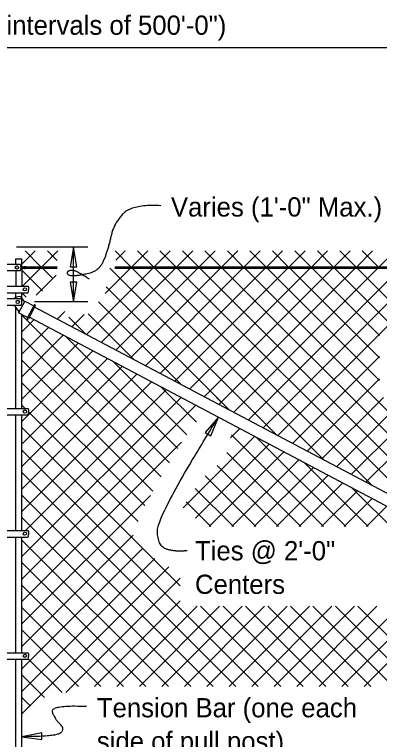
# Model space of a CAD drawing. Extents: x 110698 to 110915, y 110390 to 110472.
# Drawn here: x 110885.02 to 110888.85, y 110461.82 to 110469.42 of the extents above; entities that cross this region are included whole.
import ezdxf

# ---------------------------------------------------------------- set-up
doc = ezdxf.new("R2010")
doc.units = 0
for name, color, linetype in [('Border', 7, 'Continuous'), ('PlotBorder_dp', 7, 'Continuous'), ('SheetBorder_dp', 7, 'Continuous'), ('TextMisc', 7, 'Continuous')]:
    doc.layers.add(name, color=color, linetype=linetype)

msp = doc.modelspace()

# ---------------------------------------------------------------- linework, layer by layer
at = {"layer": 'PlotBorder_dp'}
for p, q in [((110874.8293, 110469.0764), (110894.8293, 110469.0764)), ((110885.7916, 110466.9853), (110885.0426, 110466.9853)), ((110885.6416, 110466.4105), (110885.6416, 110466.9853)), ((110885.7916, 110466.4105), (110885.2325, 110466.4105))]:
    msp.add_line(p, q, dxfattribs=at)
for points in [[(110885.6416, 110466.9853), (110885.6063, 110466.7771), (110885.6769, 110466.7771)], [(110885.6416, 110466.4105), (110885.6769, 110466.6187), (110885.6063, 110466.6187)], [(110887.1593, 110465.2015), (110887.0203, 110465.0425), (110887.0804, 110465.0055)], [(110885.1003, 110461.8521), (110885.3095, 110461.8231), (110885.3074, 110461.8936)]]:
    msp.add_lwpolyline(points, close=True, dxfattribs=at)
for points in [[(110886.5552, 110467.4191), (110886.2572, 110467.4351), (110886.0625, 110467.2327), (110886.0028, 110466.9563), (110885.9105, 110466.7344), (110885.689, 110466.6836), (110885.5782, 110466.6836), (110885.5782, 110466.7437), (110885.6705, 110466.7437), (110885.8043, 110466.6513)], [(110886.8318, 110463.8019), (110886.7009, 110463.7877), (110886.5179, 110463.855), (110886.5264, 110464.1816), (110887.1593, 110465.2015)], [(110885.7777, 110462.1679), (110885.3789, 110462.1857), (110885.4592, 110462.0189), (110885.5455, 110461.9415), (110885.4771, 110461.8521), (110885.1002, 110461.8521)]]:
    msp.add_open_spline(points, degree=2, dxfattribs=at)
at = {"layer": 'SheetBorder_dp'}
for p, q in [((110885.1002, 110466.8053), (110885.2403, 110466.9454)), ((110885.1329, 110466.9454), (110885.2996, 110466.7787)), ((110885.3094, 110466.7787), (110885.476, 110466.9454)), ((110885.3686, 110466.9454), (110885.4708, 110466.8432)), ((110886.0757, 110466.9454), (110886.2424, 110466.7787)), ((110886.0861, 110466.8483), (110886.1831, 110466.9454)), ((110886.2522, 110466.7787), (110886.4188, 110466.9454)), ((110886.3114, 110466.9454), (110886.4781, 110466.7787)), ((110886.4879, 110466.7787), (110886.6546, 110466.9454)), ((110886.5471, 110466.9454), (110886.7138, 110466.7787)), ((110886.7236, 110466.7787), (110886.8903, 110466.9454)), ((110886.7828, 110466.9454), (110886.9495, 110466.7787)), ((110886.9593, 110466.7787), (110887.126, 110466.9454)), ((110887.0185, 110466.9454), (110887.1852, 110466.7787)), ((110887.195, 110466.7787), (110887.3617, 110466.9454)), ((110887.2542, 110466.9454), (110887.4209, 110466.7787)), ((110887.4307, 110466.7787), (110887.5974, 110466.9454)), ((110887.4899, 110466.9454), (110887.6566, 110466.7787)), ((110887.6664, 110466.7787), (110887.8331, 110466.9454)), ((110887.7256, 110466.9454), (110887.8923, 110466.7787)), ((110887.9021, 110466.7787), (110888.0688, 110466.9454)), ((110887.9613, 110466.9454), (110888.128, 110466.7787)), ((110888.1378, 110466.7787), (110888.3045, 110466.9454)), ((110888.197, 110466.9454), (110888.3637, 110466.7787)), ((110888.3735, 110466.7787), (110888.5402, 110466.9454)), ((110888.4327, 110466.9454), (110888.5994, 110466.7787)), ((110888.6092, 110466.7787), (110888.7759, 110466.9454)), ((110888.6684, 110466.9454), (110888.8351, 110466.7787)), ((110888.8449, 110466.7787), (110889.0116, 110466.9454)), ((110885.1002, 110466.7423), (110885.3169, 110466.5257)), ((110885.1053, 110466.5746), (110885.2946, 110466.764)), ((110885.3143, 110466.764), (110885.4229, 110466.6553)), ((110885.7769, 110466.0677), (110886.4731, 110466.764)), ((110885.9311, 110465.9862), (110886.7088, 110466.764)), ((110885.9719, 110466.4984), (110886.2374, 110466.764)), ((110886.0214, 110466.764), (110887.772, 110465.0134)), ((110886.0853, 110465.9047), (110886.9445, 110466.764)), ((110886.2395, 110465.8232), (110887.1802, 110466.764)), ((110886.2571, 110466.764), (110888.2719, 110464.7492)), ((110886.3937, 110465.7417), (110887.4159, 110466.764)), ((110886.4928, 110466.764), (110888.7717, 110464.4851)), ((110886.5479, 110465.6602), (110887.6516, 110466.764)), ((110886.7021, 110465.5787), (110887.8873, 110466.764)), ((110886.7285, 110466.764), (110889.2716, 110464.2209)), ((110886.8563, 110465.4972), (110888.1231, 110466.764)), ((110886.9642, 110466.764), (110889.7714, 110463.9568)), ((110887.0106, 110465.4158), (110888.3588, 110466.764)), ((110887.1648, 110465.3343), (110888.5945, 110466.764)), ((110887.1999, 110466.764), (110890.0805, 110463.8834)), ((110887.319, 110465.2528), (110888.8302, 110466.764)), ((110887.4356, 110466.764), (110890.0805, 110464.1191)), ((110887.4732, 110465.1713), (110889.0659, 110466.764)), ((110887.6274, 110465.0898), (110889.3016, 110466.764)), ((110887.6713, 110466.764), (110888.8471, 110465.5882)), ((110887.7816, 110465.0083), (110889.5373, 110466.764)), ((110887.907, 110466.764), (110888.8471, 110465.8239)), ((110888.1427, 110466.764), (110888.8471, 110466.0596)), ((110888.3784, 110466.764), (110889.0161, 110466.1263)), ((110888.6141, 110466.764), (110889.2518, 110466.1263)), ((110885.2482, 110466.4818), (110885.4579, 110466.6915)), ((110885.1002, 110466.5066), (110885.1457, 110466.4612)), ((110885.9827, 110466.5669), (110887.2722, 110465.2775)), ((110885.902, 110466.412), (110886.7723, 110465.5417)), ((110885.4685, 110466.2307), (110885.5489, 110466.3111)), ((110885.6227, 110466.1492), (110885.7533, 110466.2798)), ((110885.793, 110466.2852), (110886.2725, 110465.8058)), ((110885.1002, 110466.2709), (110886.6464, 110464.7247)), ((110885.1002, 110466.0981), (110885.2255, 110466.2234)), ((110885.592, 110466.2506), (110885.7726, 110466.07)), ((110885.1002, 110465.8624), (110885.3797, 110466.1419)), ((110885.1002, 110465.6267), (110885.5339, 110466.0604)), ((110885.1002, 110466.0352), (110886.5601, 110464.5754)), ((110885.1002, 110465.391), (110885.6881, 110465.9789)), ((110885.5604, 110466.0464), (110886.7328, 110464.8741)), ((110885.1002, 110465.1553), (110885.8423, 110465.8975)), ((110887.9358, 110464.9268), (110888.8471, 110465.8381)), ((110885.1002, 110465.7995), (110886.4737, 110464.426)), ((110885.1067, 110464.9261), (110885.9965, 110465.816)), ((110886.0603, 110465.7823), (110886.8273, 110465.0153)), ((110885.1002, 110464.6839), (110886.1508, 110465.7345)), ((110885.1002, 110464.4482), (110886.305, 110465.653)), ((110888.09, 110464.8453), (110888.8471, 110465.6024)), ((110885.1002, 110464.2125), (110886.4592, 110465.5715)), ((110885.1002, 110465.5638), (110886.3874, 110464.2767)), ((110886.5601, 110465.5181), (110886.9298, 110465.1484)), ((110885.137, 110464.0136), (110886.6134, 110465.49)), ((110885.1002, 110463.7411), (110886.7676, 110465.4085)), ((110887.1404, 110465.4092), (110887.2722, 110465.2775)), ((110888.2442, 110464.7638), (110888.8896, 110465.4092)), ((110888.3984, 110464.6823), (110889.1253, 110465.4092)), ((110888.3984, 110464.6823), (110889.1253, 110465.4092)), ((110888.5526, 110464.6008), (110889.361, 110465.4092)), ((110888.5526, 110464.6008), (110889.361, 110465.4092)), ((110888.7069, 110464.5193), (110889.5967, 110465.4092)), ((110888.7069, 110464.5193), (110889.5967, 110465.4092)), ((110885.1002, 110465.3281), (110885.1343, 110465.2941)), ((110885.1002, 110463.5054), (110886.9218, 110465.327)), ((110885.1726, 110465.2558), (110886.32, 110464.1083)), ((110885.1002, 110465.0924), (110886.7577, 110463.435)), ((110887.2874, 110464.9855), (110887.3844, 110465.0825)), ((110886.7889, 110464.2513), (110887.5387, 110465.001)), ((110887.2958, 110465.0182), (110888.2597, 110464.0543)), ((110887.5598, 110464.9899), (110888.4954, 110464.0543)), ((110885.1002, 110463.2697), (110886.7715, 110464.941)), ((110886.9184, 110464.1451), (110887.6929, 110464.9196)), ((110885.1002, 110464.8567), (110887.5776, 110462.3794)), ((110887.0633, 110464.0543), (110887.8471, 110464.8381)), ((110887.2479, 110464.8304), (110888.024, 110464.0543)), ((110887.1456, 110464.6969), (110887.7883, 110464.0543)), ((110887.299, 110464.0543), (110888.0013, 110464.7566)), ((110888.0596, 110464.7257), (110888.7311, 110464.0543)), ((110885.1002, 110464.621), (110887.3419, 110462.3794)), ((110887.5347, 110464.0543), (110888.1555, 110464.6751)), ((110887.0207, 110464.5861), (110887.5526, 110464.0543)), ((110887.7704, 110464.0543), (110888.3097, 110464.5936)), ((110886.9162, 110464.4549), (110887.3168, 110464.0543)), ((110888.0061, 110464.0543), (110888.4639, 110464.5121)), ((110888.5595, 110464.4616), (110891.8943, 110461.1268)), ((110885.1002, 110464.3853), (110887.1062, 110462.3794)), ((110885.1002, 110463.034), (110886.4484, 110464.3822)), ((110888.2418, 110464.0543), (110888.6181, 110464.4306)), ((110886.8224, 110464.313), (110887.0811, 110464.0543)), ((110888.4775, 110464.0543), (110888.7723, 110464.3491)), ((110888.7132, 110464.0543), (110888.9266, 110464.2676)), ((110885.1002, 110464.1496), (110886.8705, 110462.3794)), ((110885.1002, 110462.7983), (110886.2655, 110463.9636)), ((110885.1002, 110463.9139), (110886.6348, 110462.3794)), ((110888.2168, 110462.3794), (110889.6976, 110463.8602)), ((110885.1002, 110462.5626), (110886.3602, 110463.8226)), ((110888.4525, 110462.3794), (110889.8518, 110463.7787)), ((110885.1002, 110462.3269), (110886.4929, 110463.7196)), ((110888.6882, 110462.3794), (110890.006, 110463.6972)), ((110885.1002, 110463.6782), (110886.3991, 110462.3794)), ((110885.1002, 110462.0912), (110886.6417, 110463.6327)), ((110885.5593, 110462.3145), (110886.7577, 110463.513)), ((110885.1002, 110463.4425), (110886.1634, 110462.3794)), ((110885.8598, 110462.3794), (110886.7577, 110463.2773)), ((110885.1002, 110463.2068), (110885.9277, 110462.3794)), ((110886.0955, 110462.3794), (110886.9363, 110463.2202)), ((110886.3312, 110462.3794), (110887.172, 110463.2202)), ((110886.5669, 110462.3794), (110887.4077, 110463.2202)), ((110886.8026, 110462.3794), (110887.6434, 110463.2202)), ((110886.9725, 110463.2202), (110887.8133, 110462.3794)), ((110887.0383, 110462.3794), (110887.8791, 110463.2202)), ((110887.2082, 110463.2202), (110888.049, 110462.3794)), ((110887.274, 110462.3794), (110888.1148, 110463.2202)), ((110887.4439, 110463.2202), (110888.2847, 110462.3794)), ((110887.5097, 110462.3794), (110888.3505, 110463.2202)), ((110887.6796, 110463.2202), (110888.5204, 110462.3794)), ((110887.7454, 110462.3794), (110888.5862, 110463.2202)), ((110887.9153, 110463.2202), (110888.7561, 110462.3794)), ((110887.9811, 110462.3794), (110888.8219, 110463.2202)), ((110888.151, 110463.2202), (110888.9918, 110462.3794)), ((110888.3867, 110463.2202), (110890.4801, 110461.1268)), ((110888.6224, 110463.2202), (110890.7158, 110461.1268)), ((110885.1002, 110462.9711), (110885.692, 110462.3794)), ((110885.166, 110462.6696), (110885.5202, 110462.3155)), ((110885.1002, 110462.4997), (110885.3381, 110462.2618)), ((110885.1002, 110462.264), (110885.1905, 110462.1737))]:
    msp.add_line(p, q, dxfattribs=at)
at = {"layer": 'TextMisc'}
for p, q in [((110885.0377, 110466.8058), (110885.0377, 110466.862)), ((110885.0377, 110466.862), (110885.1002, 110466.862)), ((110885.0377, 110466.8058), (110885.0377, 110466.862)), ((110885.0377, 110466.862), (110885.1002, 110466.862)), ((110885.1002, 110466.7818), (110885.1002, 110466.862)), ((110885.1002, 110466.7818), (110885.1002, 110466.862)), ((110884.6737, 110466.8058), (110885.0834, 110466.8058)), ((110884.6737, 110466.7381), (110885.0831, 110466.7381)), ((110885.0377, 110466.7381), (110885.0377, 110466.5746)), ((110885.0377, 110466.7381), (110885.0377, 110466.5746)), ((110885.0907, 110466.7833), (110885.1199, 110466.7787)), ((110885.0908, 110466.7833), (110885.1201, 110466.7787)), ((110885.0912, 110466.7629), (110885.1248, 110466.7685)), ((110885.0913, 110466.7783), (110885.1173, 110466.7743)), ((110885.0913, 110466.7629), (110885.1249, 110466.7685)), ((110885.0914, 110466.7783), (110885.1174, 110466.7743)), ((110885.0916, 110466.7677), (110885.1215, 110466.7726)), ((110885.0917, 110466.7677), (110885.1216, 110466.7726)), ((110885.1002, 110466.7769), (110885.1002, 110466.7691)), ((110885.1002, 110466.7769), (110885.1002, 110466.7691)), ((110885.1002, 110466.7644), (110885.1002, 110466.5746)), ((110885.1002, 110466.7644), (110885.1002, 110466.5746)), ((110885.1112, 110466.764), (110885.4704, 110466.764)), ((110885.1126, 110466.7787), (110885.4704, 110466.7787)), ((110886.0734, 110466.7787), (110894.5084, 110466.7787)), ((110886.0734, 110466.764), (110894.535, 110466.764)), ((110884.6737, 110466.5746), (110885.1647, 110466.5746)), ((110884.6737, 110466.507), (110885.164, 110466.507)), ((110885.0377, 110466.458), (110885.0377, 110466.5069)), ((110885.1002, 110466.4503), (110885.1002, 110466.5069)), ((110884.567, 110466.445), (110885.0918, 110466.445)), ((110885.1259, 110466.411), (110885.0912, 110466.4641)), ((110884.567, 110466.3772), (110885.0918, 110466.3772)), ((110885.0699, 110466.305), (110885.023, 110466.3767)), ((110885.0377, 110465.2941), (110885.0377, 110466.3542)), ((110885.1294, 110466.4176), (110885.0657, 110466.297)), ((110885.1294, 110466.4176), (110885.2237, 110466.3677)), ((110885.2283, 110466.3764), (110885.1558, 110466.2392)), ((110885.2402, 110466.3701), (110885.1677, 110466.233)), ((110894.482, 110461.4674), (110885.2324, 110466.3554)), ((110885.16, 110466.2471), (110885.0657, 110466.297)), ((110885.1002, 110465.2941), (110885.1002, 110466.2787)), ((110894.426, 110461.3615), (110885.1764, 110466.2494)), ((110885.0377, 110465.2941), (110885.0377, 110465.8594)), ((110885.1002, 110465.2941), (110885.1002, 110465.8247)), ((110884.6737, 110465.2941), (110885.1647, 110465.2941)), ((110884.6737, 110465.2265), (110885.164, 110465.2265)), ((110885.0377, 110464.0135), (110885.0377, 110465.2265)), ((110885.1002, 110464.0135), (110885.1002, 110465.2265)), ((110884.6737, 110464.0135), (110885.1647, 110464.0135)), ((110884.6737, 110463.9459), (110885.164, 110463.9459)), ((110885.0377, 110462.733), (110885.0377, 110463.9459)), ((110885.1002, 110462.733), (110885.1002, 110463.9459)), ((110884.6737, 110462.733), (110885.1647, 110462.733)), ((110884.6737, 110462.6654), (110885.164, 110462.6654)), ((110885.0377, 110461.4526), (110885.0377, 110462.6654)), ((110885.1002, 110461.4526), (110885.1002, 110462.6654))]:
    msp.add_line(p, q, dxfattribs=at)
for centre, start, end in [((110885.2341, 110466.3732), 332.14902, 152.14902), ((110885.1616, 110466.236), 152.14902, 332.14902)]:
    msp.add_arc(centre, 0.00673, start, end, dxfattribs=at)
for centre, major_axis in [((110885.0474, 110466.7713), (-0.0178, 0)), ((110885.0474, 110466.7713), (-0.0178, 0)), ((110885.131, 110466.5419), (-0.0177, 0)), ((110885.131, 110466.5419), (-0.0177, 0)), ((110885.0559, 110466.4105), (-0.0178, 0)), ((110885.131, 110465.2613), (-0.0177, 0)), ((110885.131, 110465.2613), (-0.0177, 0)), ((110885.131, 110463.9808), (-0.0177, 0)), ((110885.131, 110463.9808), (-0.0177, 0)), ((110885.131, 110462.7003), (-0.0177, 0)), ((110885.131, 110462.7003), (-0.0177, 0))]:
    msp.add_ellipse(centre, major_axis=major_axis, ratio=0.957868, dxfattribs=at)
for centre, major_axis, ratio, start_param, end_param in [((110885.014, 110466.7722), (0.0776, 0), 0.957868, 5.803915, 6.752041), ((110885.014, 110466.7722), (0.0776, 0), 0.957868, 5.803915, 6.752041), ((110885.1225, 110466.7689), (-0.0095, 0), 0.957868, 5.673972, 6.052579), ((110885.1225, 110466.7689), (-0.0095, 0), 0.957868, 5.673972, 6.052579), ((110885.1225, 110466.7689), (-0.0095, 0), 0.957868, 0.252467, 1.271421), ((110885.1225, 110466.7689), (-0.0095, 0), 0.957868, 0.252467, 1.271421), ((110885.1166, 110466.7647), (0.00982, 0), 0.957868, 0.655696, 1.505671), ((110885.1166, 110466.7647), (0.00982, 0), 0.957868, 0.655696, 1.505671), ((110885.1185, 110466.7696), (0.0115, -0.0041), 0.737732, 5.08821, 8.212701), ((110885.1185, 110466.7696), (0.0115, -0.0041), 0.737732, 5.08821, 8.212701), ((110885.1219, 110466.7672), (0.00301, 0), 0.957868, 3.28349, 5.170635), ((110885.1219, 110466.7672), (0.00301, 0), 0.957868, 3.28349, 5.170635), ((110885.1225, 110466.7694), (-0.00453, 0), 0.957868, 5.149727, 5.551998), ((110885.1225, 110466.7694), (-0.00453, 0), 0.957868, 5.149727, 5.551998), ((110885.1198, 110466.7681), (0.00527, 0), 0.957868, 5.058829, 7.342751), ((110885.1198, 110466.7681), (0.00527, 0), 0.957868, 5.058829, 7.342751), ((110885.1242, 110466.7705), (-0.00872, 0), 0.957868, 2.1008, 4.992926), ((110885.1242, 110466.7705), (-0.00872, 0), 0.957868, 2.1008, 4.992926), ((110885.1219, 110466.7672), (0.00301, 0), 0.957868, 0.004594, 0.141897), ((110885.1219, 110466.7672), (0.00301, 0), 0.957868, 0.004594, 0.141897), ((110885.1303, 110466.77), (0.00944, 0), 0.957868, 4.316497, 6.557353), ((110885.1303, 110466.77), (0.00944, 0), 0.957868, 4.316497, 6.557353), ((110885.1307, 110466.771), (-0.00872, 0), 0.957868, 3.323334, 4.992926), ((110885.1307, 110466.771), (-0.00872, 0), 0.957868, 3.323334, 4.992926), ((110885.1307, 110466.771), (-0.00503, 0), 0.92697, 1.780895, 4.712389), ((110885.1307, 110466.771), (-0.00503, 0), 0.92697, 1.780895, 4.712389), ((110885.1355, 110466.7655), (-0.0142, 0), 0.957868, 3.141593, 4.79635), ((110885.1355, 110466.7655), (-0.0142, 0), 0.957868, 3.141593, 4.79635), ((110885.1274, 110466.7504), (0.0274, 0), 0.957868, 0.628521, 1.149654), ((110885.1274, 110466.7504), (0.0274, 0), 0.957868, 0.628521, 1.149654), ((110885.0951, 110466.5414), (0.0776, 0), 0.957868, 5.801244, 6.745158), ((110885.0951, 110466.5414), (0.0776, 0), 0.957868, 5.801244, 6.745158), ((110885.0746, 110466.3958), (-0.0647, 0.0342), 0.957868, 4.95193, 6.011789), ((110885.0226, 110466.4109), (0.0776, 0), 0.957868, 5.810211, 6.75616), ((110885.0951, 110465.2609), (0.0776, 0), 0.957868, 5.801046, 6.744962), ((110885.0951, 110465.2609), (0.0776, 0), 0.957868, 5.801046, 6.744962), ((110885.0951, 110463.9804), (0.0776, 0), 0.957868, 5.800848, 6.744767), ((110885.0951, 110463.9804), (0.0776, 0), 0.957868, 5.800848, 6.744767), ((110885.0951, 110462.6999), (0.0776, 0), 0.957868, 5.810211, 6.745158), ((110885.0951, 110462.6999), (0.0776, 0), 0.957868, 5.810211, 6.745158)]:
    msp.add_ellipse(centre, major_axis=major_axis, ratio=ratio, start_param=start_param, end_param=end_param, dxfattribs=at)

# ---------------------------------------------------------------- texts
at = {"layer": 'Border'}
for s, p in [('Pull Post Assembly (required at maximum intervals of 500\'-0")', (110879.8593, 110469.2113)), ('Varies (1\'-0" Max.)  (Typ.)', (110886.6617, 110467.3055))]:
    msp.add_text(s, height=0.2016, dxfattribs=at).set_placement(p)
at = {"layer": 'PlotBorder_dp'}
for s, p in [('Ties @ 2\'-0" ', (110886.9142, 110463.7014)), ('Centers', (110886.9142, 110463.3494)), ('Tension Bar (one each ', (110885.8855, 110462.0556)), ('side of pull post)', (110885.8855, 110461.7036))]:
    msp.add_text(s, height=0.2016, dxfattribs=at).set_placement(p)

doc.saveas('drawing.dxf')
